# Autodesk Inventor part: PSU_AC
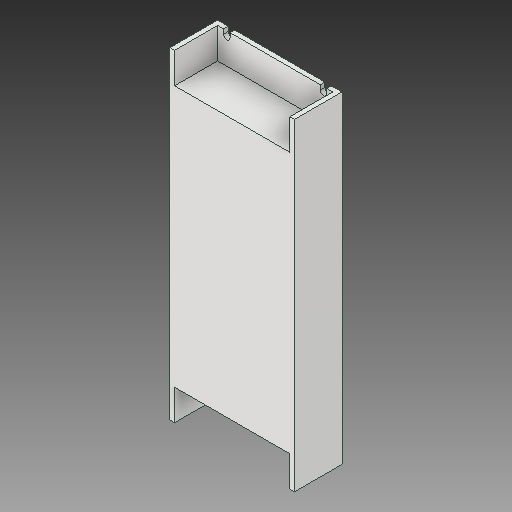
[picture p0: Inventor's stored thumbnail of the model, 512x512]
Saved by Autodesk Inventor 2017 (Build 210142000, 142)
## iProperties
Created: 2017-05
Part Number: PSU_AC
Material: Generic
Document SubType Name: Modeling
Designer: Savy
Density: 1 g/cm^3
Appearance: Default
Mass: 443.076 g
Surface Area: 542.466 cm^2
Volume: 443.076 cm^3
Author: Savy
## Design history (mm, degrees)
feature "SOLID1"
body "Solid1"
